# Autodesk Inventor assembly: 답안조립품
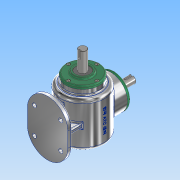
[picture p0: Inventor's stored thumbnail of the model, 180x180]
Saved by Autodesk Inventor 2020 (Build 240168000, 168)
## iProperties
Created: 2023-01
Part Number: 답안조립품
Document SubType Name: Assembly
Designer: user
Author: user
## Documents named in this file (12)
- C:\Users\user\Desktop\730106V1029\답안조립품.iam
- C:\Users\user\Desktop\730106V1029\본체.ipt
- C:\Users\user\Desktop\730106V1029\오일실 17 32 8.ipt
- C:\Users\user\Desktop\730106V1029\커버.ipt
- C:\Users\user\Desktop\730106V1029\서브 축.ipt
- 서브 축.ipt
- C:\Users\user\Desktop\730106V1029\서브 베벨기어.ipt
- C:\Users\user\Desktop\730106V1029\메인 축.ipt
- 메인 축.ipt
- C:\Users\user\Desktop\730106V1029\메인 베벨기어.ipt
- C:\Users\user\Desktop\730106V1029\베어링 6203.ipt
- C:\Users\user\Desktop\730106V1029\M4.ipt
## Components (8 placed, 1 different names)
1. M4:1
2. M4:2
3. M4:3
4. M4:4
5. M4:5
6. M4:6
7. M4:7
8. M4:8
